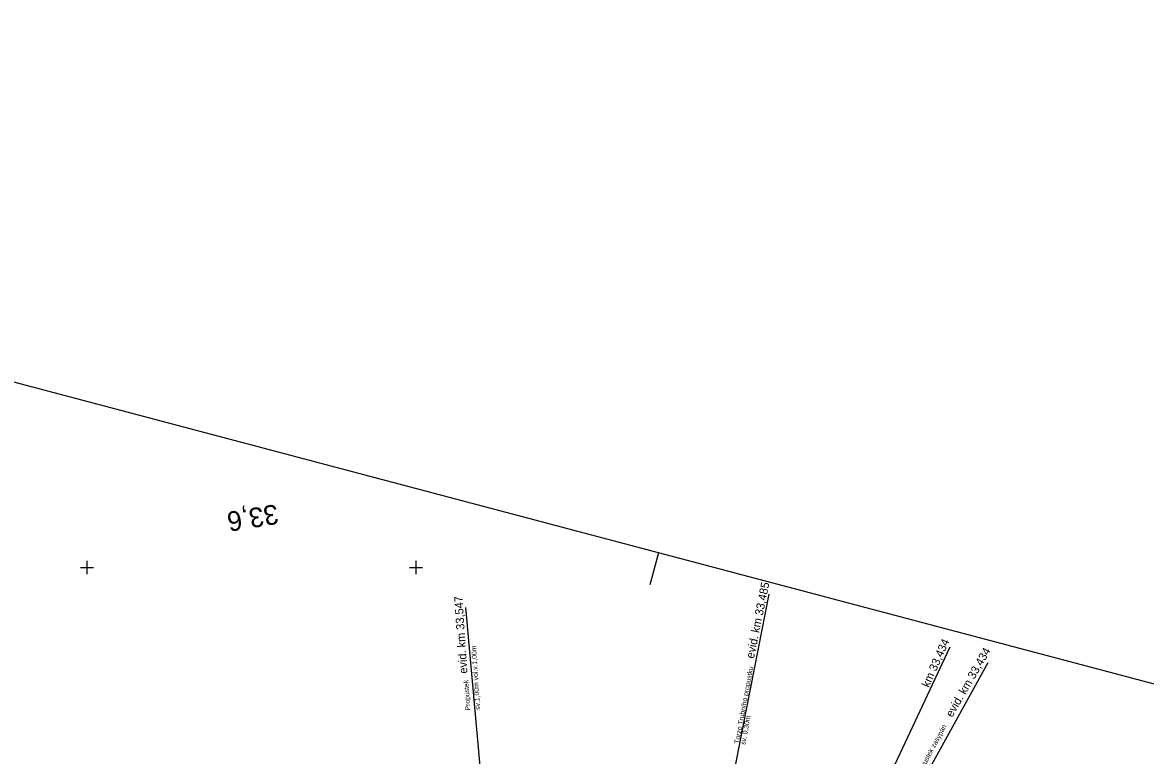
# Model space of a CAD drawing. Extents: x -805011 to -803920, y -1150790 to -1150234.
# Drawn here: x -804519.6 to -804178.2, y -1150457.1 to -1150234.4 of the extents above; entities that cross this region are included whole.
import ezdxf

# ---------------------------------------------------------------- set-up
doc = ezdxf.new("R2010")
doc.units = 0
for name, color, linetype in [('0381KM032-037P - Vrstva 19', 7, 'Continuous'), ('0381KM032-037P - Vrstva 7', 7, 'Continuous'), ('0381KM032-037P - Vrstva 9', 7, 'Continuous'), ('formát', 7, 'Continuous'), ('krizky_1000 - Vrstva 1', 7, 'Continuous')]:
    doc.layers.add(name, color=color, linetype=linetype)

msp = doc.modelspace()

# ---------------------------------------------------------------- linework, layer by layer
at = {"layer": '0381KM032-037P - Vrstva 19'}
for p, q in [((-804304.23, -1150467.13), (-804292.59, -1150408.12)), ((-804384.94, -1150412.13), (-804379.37, -1150473.64)), ((-804260.8, -1150491.55), (-804226.07, -1150428.82))]:
    msp.add_line(p, q, dxfattribs=at)
at = {"layer": '0381KM032-037P - Vrstva 9'}
msp.add_line((-804237.76, -1150424.25), (-804266.81, -1150486.01), dxfattribs=at)
at = {"layer": 'formát'}
for p, q in [((-804326.3, -1150395.58), (-804935.34, -1150234.42)), ((-804326.3, -1150395.58), (-804328.86, -1150405.25)), ((-804123.29, -1150449.3), (-804326.3, -1150395.58))]:
    msp.add_line(p, q, dxfattribs=at)
at = {"layer": 'krizky_1000 - Vrstva 1'}
for points in [[(-804500, -1150398), (-804500, -1150402)], [(-804400, -1150398), (-804400, -1150402)], [(-804502, -1150400), (-804498, -1150400)], [(-804402, -1150400), (-804398, -1150400)]]:
    msp.add_lwpolyline(points, dxfattribs=at)

# ---------------------------------------------------------------- texts
at = {"layer": '0381KM032-037P - Vrstva 19'}
for s, height, rotation, p in [('evid. km 33,485', 2.5, 78.3248, (-804297.3, -1150427.82)), ('evid. km 33,547', 2.5, 93.6992, (-804384.35, -1150432.18)), ('sv.1,00m vol.v.1,00m', 1.5, 93.6992, (-804380.47, -1150443.2)), ('evid. km 33,434', 2.5, 59.9738, (-804237.01, -1150445.7)), ('Torzo Trubního propustku', 1.5, 79.3888, (-804301.81, -1150453.61)), ('Propustek', 1.5, 93.6992, (-804383.47, -1150443.4)), ('sv. 0,30m', 1.5, 79.3888, (-804299.9, -1150453.96)), ('Trubní propustek zasypán', 1.5, 61.9777, (-804249.91, -1150469.3))]:
    msp.add_text(s, height=height, rotation=rotation, dxfattribs=at).set_placement(p)
at = {"layer": '0381KM032-037P - Vrstva 7'}
msp.add_text('33,6', height=6, rotation=189.2666, dxfattribs=at).set_placement((-804442.34, -1150380.71))
at = {"layer": '0381KM032-037P - Vrstva 9'}
msp.add_text('km 33,434', height=2.5, rotation=66.1318, dxfattribs=at).set_placement((-804244.09, -1150436.64))

doc.saveas('drawing.dxf')
